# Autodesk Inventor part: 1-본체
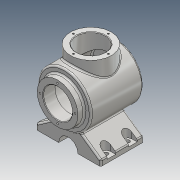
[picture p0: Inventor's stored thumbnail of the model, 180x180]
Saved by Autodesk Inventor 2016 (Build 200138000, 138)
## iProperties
Created: 2017-04
Part Number: 1-본체
Material: 알루미늄 6061
Document SubType Name: Modeling
Designer: CAMTIC
Density: 2.7 g/cm^3
Appearance: 알루미늄 - 평지
Mass: 1664.52 g
Surface Area: 1066.89 cm^2
Volume: 616.49 cm^3
Author: CAMTIC
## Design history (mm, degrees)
sketch "스케치1"
  geometry: L1 (-62, 0)-(-50, 0); L2 (-50, 0)-(-50, 38); L3 (-50, 38)-(-62, 38); L4 (-62, 38)-(-62, 0); L5 (-50, 0)-(46.336, 0); L6 (46.336, 0)-(46.336, 50); L7 (46.336, 50)-(-50, 50); L8 (-50, 50)-(-50, 0); L9 (46.336, 0)-(58, 0); A1 r 113 centre (-55, 0) between (58, 0) and (46.336, 50); 1 further point
  constraints: 18 end point, 4 parallel, 2 horizontal, 2 perpendicular, 2 point on circle, 2 point on line, 1 centre point, 1 collinear
  dimensions: "d0" = 108 distance from line of L9.end L2; "d1" = 12 distance between parallel lines of L2 L4; "d2" = 76 diameter of L3 L1; "d3" = 100 diameter of L7 L5; "d5" = 113 radius of A1; "d6" = 50 distance from line of point (0, 0) L2
revolve "회전1" sketch "스케치1" stored, may be unused: angle "d7" = 90 deg
sketch "스케치3"
  geometry: L1 (60, -82)-(-60, -82); L2 (-60, -82)-(-60, -72); L3 (-60, -72)-(60, -72); L4 (60, -72)-(60, -82); L5 (60, -72)-(21.584, -45.101); L6 (21.584, -45.101)-(-21.584, -45.101); L7 (-21.584, -45.101)-(-60, -72); C1 r 18 at (0, -82); 3 further points
  constraints: 14 end point, 2 horizontal, 2 parallel, 1 centre point, 1 coincident, 1 equal length, 1 midpoint, 1 perpendicular, 1 vertical alignment, 2 other
  dimensions: "d11" = 55 deg angle of L2 L7; "d12" = 120 distance of L1.start L1.end; "d13" = 10 distance of L1.end L2.end; "d14" = 82 distance from line of L1 point (0, 0); "d16" = 18 radius of C1
extrude "돌출1" join sketch "스케치3" distance "d17" = 38; taper "d18" = 0 deg; dims "d56" = 42, "d57" = 0
extrude "돌출2" cut sketch "스케치3" stored distance "d19" = 80; taper "d20" = 0 deg
sketch "스케치6"
  geometry: L1 (0, 0)-(38, 0); L2 (38, 0)-(38, 65); L3 (38, 65)-(0, 65); L4 (0, 65)-(0, 0); L5 (38, -82)-(-42, -82) reference; 1 further point
  constraints: 8 end point, 2 parallel, 1 coincident, 1 horizontal, 1 perpendicular
  dimensions: "d24" = 147 distance between parallel lines of L5 L3; "d25" = 76 diameter of L2 L4
revolve "회전3" sketch "스케치6" stored, may be unused: angle "d26" = 90 deg
sketch "스케치7"
  geometry: L1 (-62, 0)-(-40, 0); L2 (-40, 0)-(-40, 27); L3 (-40, 27)-(-62, 27); L4 (-62, 27)-(-62, 0); L5 (-40, 0)-(39.916, 0); L6 (39.916, 0)-(39.916, 40); L7 (39.916, 40)-(-40, 40); L8 (-40, 40)-(-40, 0); L9 (39.916, 0)-(48, 0); L10 (-62, -38)-(-62, 38) reference; A1 r 113 centre (-55, 0) between (46.336, -50) and (46.336, 50) reference; A2 r 103 centre (-55, 0) between (48, 0) and (39.916, 40); 1 further point
  constraints: 18 end point, 4 parallel, 2 collinear, 2 horizontal, 2 perpendicular, 2 point on circle, 1 centre point, 1 coincident, 1 point on line
  dimensions: "d27" = 103 radius of A2; "d28" = 80 diameter of L7 L5; "d29" = 22 distance between parallel lines of L2 L4; "d30" = 54 diameter of L3 L1
revolve "회전4" sketch "스케치7" stored, may be unused: angle "d31" = 90 deg
hole "구멍1" diameter "d34" = 54; stored, may be unused: countersink angle "d38" = 90 deg, drill point angle "d40" = 118 deg; dims "d32" = 10, "d33" = 10, "d35" = 6, "d36" = 4, "d37" = 2, "d39" = 8
node "작업 평면1"
fillet "모깎기1" dims "d77" = 3
fillet "모깎기2" dims "d78" = 3
fillet "모깎기3" dims "d79" = 3
chamfer "모따기1" distance "d80" = 1; stored, may be unused: second distance "d81" = 2, angle "d82" = 45 deg
sketch "스케치9"
  geometry: L1 (10, 20)-(0, 20); L2 (10, 28)-(0, 28); L3 (0, 12)-(10, 12); L4 (42, 0)-(0, 0) reference; L5 (0, 0)-(0, 80) reference; L6 (10, 20)-(10, 60); L7 (0, 80)-(42, 80) reference; A1 r 8 centre (10, 20) between (10, 12) and (10, 28); A2 r 8 centre (0, 20) between (0, 28) and (0, 12); 2 further points
  constraints: 10 end point, 4 point on circle, 4 tangent, 2 centre point, 1 horizontal, 1 midpoint, 1 parallel, 1 point on line, 1 vertical
  dimensions: "d58" = 16 distance between parallel lines of L2 L3; "d59" = 20 distance from line of L4 L1.start; "d60" = 10 distance from line of L5 L1.start; "d72" = 20 distance from line of L7 L6.end; "d73" = 40 distance of L1.start L6.end (derived)
extrude "돌출4" cut sketch "스케치9" distance "d61" = 30; taper "d62" = 0 deg
hole "구멍3" diameter "d65" = 8; stored, may be unused: countersink angle "d69" = 90 deg, drill point angle "d71" = 118 deg; dims "d63" = 10, "d64" = 10, "d66" = 6, "d67" = 4, "d68" = 2, "d70" = 8
sketch "스케치10" dims "d84" = 65
  geometry: 3 further points
  constraints: 2 vertical alignment, 1 coincident, 2 other
hole "구멍4" sketch "스케치10" at (0, 32.5) diameter "d85" = 3.242; stored, may be unused: countersink angle "d89" = 90 deg, drill point angle "d91" = 118 deg; dims "d86" = 8, "d87" = 4, "d88" = 2, "d90" = 10
sketch "스케치11" dims "d95" = 65
  geometry: 3 further points
  constraints: 2 vertical alignment, 1 coincident, 2 other
hole "구멍5" sketch "스케치11" at (0, 32.5) diameter "d96" = 3.242; stored, may be unused: countersink angle "d100" = 90 deg, drill point angle "d102" = 118 deg; dims "d97" = 8, "d98" = 4, "d99" = 2, "d101" = 10
node "엠보싱 평면"
sketch "스케치12"
  geometry: 2 further points
  constraints: 1 coincident, 1 other
feature "엠보싱1" sketch "스케치12" dims "d0" = 108, "d1" = 12, "d2" = 76, "d3" = 100, "d5" = 113, "d6" = 50, "d107" = 0.5, "d108" = 0
node "솔리드1"
pattern_linear "직사각형 패턴1"
mirror "대칭3"
pattern_circular "원형 패턴1" dims angle "d93" = 360 deg
pattern_circular "원형 패턴2" dims angle "d104" = 360 deg
other parameters: "d41" = -6, "d106" = 130.5
